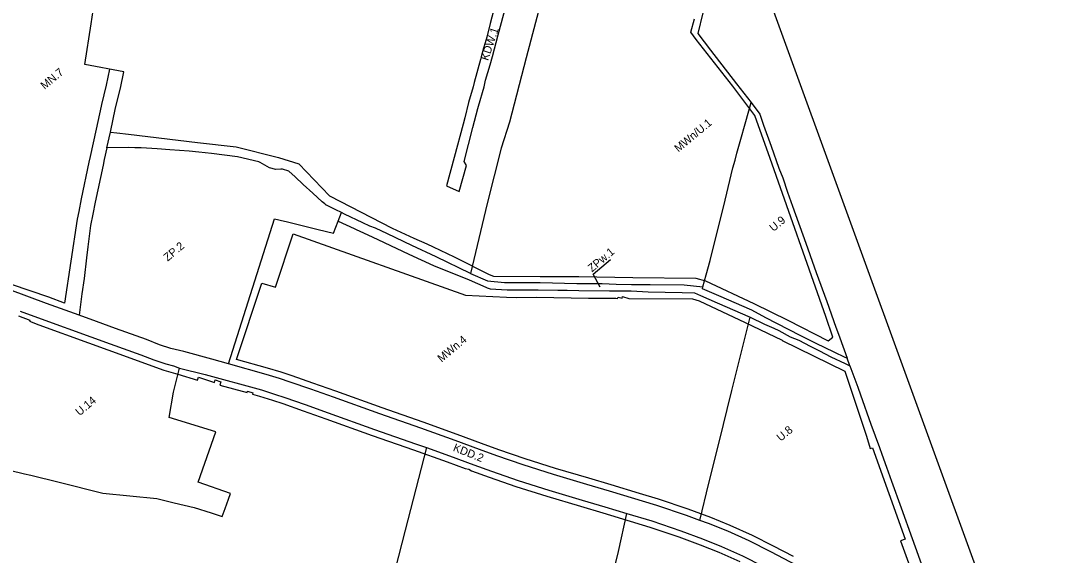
# Model space of a CAD drawing. Extents: x 7418616 to 7420822, y 5550745 to 5553106.
# Drawn here: x 7420140 to 7420789, y 5551619 to 5551953 of the extents above; entities that cross this region are included whole.
import ezdxf

# ---------------------------------------------------------------- set-up
doc = ezdxf.new("R2010")
doc.units = 0
for name, color, linetype in [('granica obszaru objętego planem', 7, 'Continuous'), ('linie rozgraniczające', 7, 'Continuous'), ('nieprzekraczalne linie zabudowy', 7, 'Continuous'), ('przeznaczenia terenów', 7, 'Continuous')]:
    doc.layers.add(name, color=color, linetype=linetype)

msp = doc.modelspace()

# ---------------------------------------------------------------- linework, layer by layer
at = {"layer": 'granica obszaru objętego planem'}
msp.add_lwpolyline([(7420419.04, 5552462.29), (7420427.01, 5552448.46), (7420437.26, 5552429.47), (7420442.19, 5552419.71), (7420448.72, 5552405.7), (7420457.17, 5552386.45), (7420461.96, 5552374), (7420467.81, 5552358.36), (7420579.74, 5552042.73), (7420611.64, 5551954.27), (7420788.95, 5551466.82)], dxfattribs=at)
at = {"layer": 'linie rozgraniczające'}
for p, q in [((7420338.05, 5551827.75), (7420340.15, 5551833.05)), ((7420654.02, 5551747.44), (7420655.91, 5551742.21)), ((7420657.64, 5551737.41), (7420655.91, 5551742.21))]:
    msp.add_line(p, q, dxfattribs=at)
for points in [[(7420419.04, 5552462.29), (7420427.01, 5552448.46), (7420437.26, 5552429.47), (7420442.19, 5552419.71), (7420448.72, 5552405.7), (7420457.17, 5552386.45), (7420461.96, 5552374), (7420467.81, 5552358.36), (7420579.74, 5552042.73), (7420611.64, 5551954.27), (7420788.95, 5551466.82)], [(7420193.57, 5551873.49), (7420195.82, 5551883.31), (7420198.98, 5551898.48), (7420202.06, 5551910.66), (7420204.15, 5551920.87), (7420179.92, 5551925.55), (7420183.78, 5551950.94), (7420185.03, 5551959.25), (7420186.02, 5551965.86), (7420186.46, 5551968.78), (7420187.03, 5551972.47), (7420187.29, 5551974.18), (7420188.03, 5551979.07), (7420190.09, 5551992.79), (7420192.66, 5551992.53), (7420230.5, 5551986.79), (7420231.69, 5551995.09), (7420233, 5552002.11), (7420234.81, 5552008.88), (7420235.65, 5552015.65), (7420235.1, 5552018.04), (7420234.95, 5552018.56), (7420235.55, 5552023.03), (7420237.91, 5552040.62)], [(7420475.4, 5552004.42), (7420468.68, 5551980.21), (7420466.09, 5551970.04), (7420455.5, 5551929.73), (7420444.96, 5551889.52), (7420439.84, 5551873.32), (7420431, 5551838.75), (7420420.77, 5551795.07)], [(7420435.02, 5551959.02), (7420432.98, 5551951.04), (7420430.82, 5551942.66), (7420429.78, 5551938.99), (7420428.82, 5551935.63), (7420427.37, 5551930.37), (7420426.91, 5551928.66), (7420423.07, 5551914.35), (7420422.35, 5551911.64), (7420419.51, 5551901.86), (7420417.16, 5551892.29), (7420416.04, 5551888.17), (7420410.47, 5551867.41), (7420405.72, 5551849.75), (7420413.67, 5551846.22), (7420418.25, 5551862.39), (7420416.7, 5551864.88), (7420422.21, 5551886.13), (7420425.3, 5551898.02), (7420425.69, 5551899.5), (7420429.15, 5551911.64), (7420430.15, 5551915.7), (7420433.02, 5551925.35), (7420434.41, 5551930.56), (7420437.88, 5551943.99), (7420444.41, 5551968.18)], [(7420565.81, 5551957.74), (7420562.67, 5551944.97), (7420570.65, 5551934.55), (7420586.79, 5551913.47), (7420595.95, 5551901.87)], [(7420565.79, 5551786.62), (7420567.78, 5551794.28), (7420570.32, 5551803.16), (7420579.82, 5551840.9), (7420584.55, 5551861.06), (7420585.91, 5551865.75), (7420587.09, 5551870.08), (7420589.19, 5551877.53), (7420592.6, 5551889.95), (7420595.95, 5551901.87)], [(7420595.95, 5551901.87), (7420601.27, 5551894.57), (7420603.59, 5551887.71), (7420608.4, 5551874.62), (7420613.28, 5551860.87), (7420615.75, 5551854.67), (7420618.72, 5551845.89), (7420621.82, 5551837.01), (7420630.07, 5551813.93), (7420635.31, 5551799.28), (7420636.59, 5551795.72), (7420643.11, 5551777.66), (7420648.9, 5551761.61), (7420650.52, 5551757.14), (7420654.02, 5551747.44)], [(7420193.57, 5551873.49), (7420191.9, 5551866.18), (7420191.22, 5551862.75), (7420186.41, 5551839.62), (7420184.95, 5551832.03), (7420183.4, 5551824.97), (7420181.82, 5551811.76), (7420180.97, 5551804.76), (7420179.39, 5551791.89), (7420178, 5551782.42), (7420176.22, 5551769.04)], [(7420340.15, 5551833.05), (7420336.66, 5551834.73), (7420330.73, 5551837.64), (7420330.65, 5551837.7), (7420329.65, 5551838.52), (7420328.15, 5551839.84), (7420322.24, 5551845.23), (7420316.3, 5551850.6), (7420311.16, 5551855.35), (7420307.24, 5551859), (7420303.27, 5551860.19), (7420302.28, 5551860.14), (7420299.19, 5551859.93), (7420295.13, 5551861.02), (7420289.33, 5551864.37), (7420288.45, 5551864.84), (7420275.11, 5551867.93), (7420258.93, 5551869.93), (7420250.97, 5551870.77), (7420245, 5551871.32), (7420239.02, 5551871.84), (7420233.04, 5551872.31), (7420225.06, 5551872.87), (7420215.08, 5551873.53), (7420211.08, 5551873.6), (7420207.08, 5551873.64), (7420193.57, 5551873.49)], [(7420269.61, 5551738.62), (7420298.26, 5551829.25), (7420304.48, 5551827.71), (7420305.49, 5551827.46), (7420314.72, 5551825.19), (7420325.66, 5551822.53)], [(7420420.77, 5551795.07), (7420399.26, 5551805.5), (7420383.96, 5551812.62), (7420368.78, 5551819.84), (7420361.34, 5551823.34), (7420357.85, 5551824.54), (7420353.55, 5551826.64), (7420342.04, 5551832.14), (7420340.15, 5551833.05)], [(7420325.66, 5551822.53), (7420335.05, 5551820.23), (7420338.05, 5551827.75)], [(7420338.05, 5551827.75), (7420347.96, 5551823.13), (7420349.29, 5551822.51), (7420351.53, 5551821.47), (7420359.35, 5551817.88), (7420366.84, 5551814.34), (7420382.19, 5551807.19), (7420397.62, 5551800), (7420419.84, 5551791.08), (7420430.22, 5551786.42), (7420431.1, 5551786.05), (7420432.88, 5551785.53), (7420443.61, 5551784.93), (7420450.46, 5551784.85), (7420462.92, 5551784.91), (7420475.14, 5551784.66), (7420480.97, 5551784.55), (7420488.28, 5551784.42), (7420507.44, 5551784.26), (7420520.99, 5551784.28), (7420531.65, 5551783.6), (7420552.91, 5551783.17), (7420560.66, 5551783.08), (7420564.41, 5551781.27), (7420574.64, 5551776.81), (7420595.34, 5551767.85)], [(7420176.22, 5551769.04), (7420156.02, 5551776.41), (7420132.92, 5551784.81), (7420112.92, 5551791.86), (7420106.31, 5551793.86), (7420104.19, 5551797.21)], [(7420420.77, 5551795.07), (7420431.22, 5551790.39), (7420441.9, 5551789.38), (7420464.16, 5551789.36), (7420487.11, 5551788.86), (7420494.52, 5551788.84), (7420502.91, 5551788.71), (7420511.72, 5551788.46), (7420521.22, 5551788.12), (7420526.02, 5551788.16), (7420532.88, 5551788.27), (7420554.22, 5551787.95), (7420565.79, 5551786.62)], [(7420655.91, 5551742.21), (7420654.66, 5551742.7), (7420647.76, 5551745.87), (7420636.51, 5551751.36), (7420626.5, 5551756.28), (7420605.19, 5551767.47), (7420596.39, 5551772.13), (7420575.73, 5551781.01), (7420565.49, 5551785.45), (7420565.79, 5551786.62)], [(7420139.57, 5551771.54), (7420152.53, 5551766.83), (7420183.58, 5551755.49), (7420195.6, 5551751.2), (7420214.77, 5551744.27), (7420223, 5551741.05), (7420230.5, 5551738.58), (7420235.25, 5551737.38), (7420238.91, 5551736.05)], [(7420269.61, 5551738.62), (7420259.16, 5551741.52), (7420241.71, 5551746.28), (7420233.51, 5551748.33), (7420226.58, 5551750.61), (7420218.3, 5551753.84), (7420199.05, 5551760.79), (7420187.06, 5551765.08), (7420176.22, 5551769.04)], [(7420563.98, 5551640.89), (7420569.57, 5551664.22), (7420577.46, 5551695.58), (7420578.76, 5551700.83), (7420581.07, 5551710.14), (7420583.97, 5551722.05), (7420595.34, 5551767.85)], [(7420595.34, 5551767.85), (7420604.2, 5551763.43), (7420610.07, 5551760.86), (7420613.28, 5551759.43), (7420620.32, 5551755.53), (7420625.76, 5551753.4), (7420632.88, 5551749.62), (7420638.56, 5551746.67), (7420645.76, 5551743.03), (7420654.57, 5551738.81), (7420657.64, 5551737.41)], [(7420563.98, 5551640.89), (7420555.52, 5551644.01), (7420536.95, 5551650.29), (7420507.42, 5551659.25), (7420493.38, 5551663.35), (7420472.58, 5551669.53), (7420453.64, 5551675.59), (7420437.14, 5551681.27), (7420426.25, 5551685.16), (7420411.05, 5551690.86), (7420389.71, 5551698.42), (7420364.1, 5551707.37), (7420335.16, 5551717.75), (7420320.95, 5551722.8), (7420308.12, 5551727.3), (7420301.33, 5551729.53), (7420293.04, 5551732.1), (7420269.61, 5551738.62)], [(7420657.64, 5551737.41), (7420657.66, 5551737.35), (7420662.48, 5551723.99), (7420664.17, 5551719.3), (7420670.77, 5551701.04), (7420676.02, 5551686.48), (7420677.51, 5551682.36), (7420680.54, 5551674.12), (7420683.66, 5551665.32), (7420689.62, 5551648.81), (7420696.56, 5551629.55), (7420703.22, 5551611.13), (7420709.97, 5551592.42), (7420716.81, 5551573.46), (7420715.46, 5551565.97)], [(7420118.45, 5551675.77), (7420123.97, 5551674.44), (7420142.25, 5551670.08), (7420146.23, 5551669.09), (7420163.91, 5551664.7), (7420191.08, 5551657.95), (7420224.74, 5551654.62), (7420235.68, 5551651.83), (7420248.2, 5551648.89), (7420258.83, 5551645.64), (7420259.47, 5551645.41), (7420265.63, 5551643.27), (7420267.41, 5551648.29), (7420269.47, 5551654.1), (7420270.73, 5551657.71), (7420250.63, 5551664.82), (7420261.72, 5551696.13), (7420232.55, 5551705.25), (7420235.19, 5551721.06), (7420238.91, 5551736.05)], [(7420238.91, 5551736.05), (7420255.01, 5551732.08), (7420290.09, 5551722.34), (7420298.27, 5551719.8), (7420304.85, 5551717.64), (7420317.55, 5551713.18), (7420331.73, 5551708.14), (7420360.68, 5551697.76), (7420386.33, 5551688.8), (7420393.2, 5551686.36)], [(7420393.2, 5551686.36), (7420379.89, 5551634.75), (7420369.22, 5551593.33), (7420349.6, 5551520.43), (7420344.48, 5551500.75)], [(7420393.2, 5551686.36), (7420407.51, 5551681.29), (7420422.79, 5551675.56), (7420433.79, 5551671.64), (7420450.47, 5551665.89), (7420469.52, 5551659.79), (7420490.5, 5551653.57), (7420504.48, 5551649.48), (7420518.37, 5551645.27)], [(7420470.48, 5551450.29), (7420474.34, 5551465.31), (7420489.31, 5551524.58), (7420494.68, 5551545.81), (7420494.71, 5551545.91), (7420503.09, 5551580.48), (7420513.15, 5551621.48), (7420518.37, 5551645.27)], [(7420518.37, 5551645.27), (7420533.91, 5551640.55), (7420552.06, 5551634.41), (7420565.64, 5551629.41), (7420577.38, 5551624.71), (7420590.52, 5551618.8), (7420603.34, 5551612.34)], [(7420715.46, 5551565.97), (7420680.95, 5551583.37), (7420641.65, 5551603.74), (7420620.61, 5551614.78), (7420608.14, 5551621.35), (7420594.81, 5551628.06), (7420581.33, 5551634.12), (7420569.37, 5551638.91), (7420563.98, 5551640.89)]]:
    msp.add_lwpolyline(points, dxfattribs=at)
at = {"layer": 'nieprzekraczalne linie zabudowy'}
for points in [[(7420195.82, 5551883.31), (7420199.93, 5551882.85), (7420207.2, 5551881.99), (7420250.28, 5551876.86), (7420274.29, 5551874.07), (7420300.78, 5551867.36), (7420313.59, 5551863.44), (7420332.58, 5551843.56), (7420371.68, 5551823.4), (7420385.24, 5551817.19), (7420393.44, 5551813.58), (7420397.34, 5551811.78), (7420410.41, 5551805.36), (7420432.38, 5551794.5), (7420435.06, 5551793.46), (7420464.26, 5551793.27), (7420488.34, 5551793.19), (7420522.04, 5551792.5), (7420561.31, 5551792.08), (7420567.48, 5551790.37), (7420597.6, 5551776.38), (7420618.88, 5551765.84), (7420644.08, 5551752.93), (7420647.04, 5551755.24), (7420642.66, 5551768.19), (7420607.86, 5551866.8), (7420598.3, 5551893.78), (7420584.42, 5551911.93), (7420561.51, 5551941.19), (7420558.22, 5551945.61), (7420560.49, 5551954.08)], [(7420195.31, 5551922.58), (7420193.28, 5551912.67), (7420190.24, 5551900.61), (7420190, 5551899.61), (7420187.03, 5551885.23), (7420183.1, 5551868.06), (7420182.4, 5551864.54), (7420177.63, 5551841.56), (7420176.14, 5551833.85), (7420175.05, 5551828.89), (7420167.2, 5551776.59), (7420157.4, 5551780.17), (7420122.15, 5551792.15)], [(7420274.65, 5551741.37), (7420290.29, 5551789.03), (7420299.02, 5551786.45), (7420309.88, 5551819.73), (7420417.58, 5551781.56), (7420443.13, 5551780.25), (7420449.42, 5551780.09), (7420461.99, 5551780.36), (7420494.37, 5551779.7), (7420511.54, 5551779.56), (7420512.52, 5551779.47), (7420512.82, 5551780.21), (7420515.37, 5551779.57), (7420515.61, 5551780.6), (7420519.53, 5551779.5), (7420559.32, 5551779.18), (7420563.48, 5551777.9), (7420592.16, 5551764.54), (7420615.24, 5551753.33), (7420615.34, 5551753.32), (7420654.4, 5551734.12), (7420667.9, 5551693.43), (7420670.34, 5551685.89), (7420671.63, 5551686.3), (7420692.2, 5551629.25), (7420689.3, 5551628.15), (7420695.9, 5551609.77)], [(7420138.46, 5551768.6), (7420145.51, 5551766), (7420145.23, 5551765.22), (7420151.16, 5551763.07), (7420182.24, 5551751.72), (7420194.25, 5551747.43), (7420229.25, 5551734.78), (7420237.95, 5551732.17), (7420250.22, 5551728.44), (7420250.9, 5551730.38), (7420260.89, 5551727.05), (7420261.33, 5551728.72), (7420264.82, 5551727.44), (7420264.13, 5551725.4), (7420281.14, 5551720.67), (7420281.4, 5551721.56), (7420284.84, 5551720.62), (7420284.61, 5551719.71), (7420288.96, 5551718.5), (7420297.05, 5551715.99), (7420303.56, 5551713.85), (7420316.23, 5551709.41), (7420330.38, 5551704.37), (7420359.36, 5551693.98), (7420385, 5551685.02), (7420406.14, 5551677.53), (7420417.29, 5551673.35), (7420419.59, 5551672.88), (7420421.34, 5551671.83), (7420432.42, 5551667.88), (7420449.06, 5551662.14), (7420468.3, 5551655.98), (7420489.36, 5551649.73), (7420503.35, 5551645.64), (7420532.68, 5551636.75), (7420550.73, 5551630.64), (7420564.21, 5551625.68), (7420575.82, 5551621.03), (7420588.8, 5551615.19)], [(7420622.47, 5551618.32), (7420609.97, 5551624.91), (7420596.74, 5551631.57), (7420582.86, 5551637.82), (7420570.8, 5551642.64), (7420556.68, 5551647.84), (7420538.11, 5551654.12), (7420526.21, 5551657.74), (7420508.58, 5551663.07), (7420494.51, 5551667.19), (7420473.76, 5551673.35), (7420454.9, 5551679.38), (7420438.46, 5551685.05), (7420427.63, 5551688.91), (7420412.42, 5551694.62), (7420391.06, 5551702.19), (7420365.44, 5551711.14), (7420336.51, 5551721.51), (7420322.3, 5551726.57), (7420309.41, 5551731.09), (7420302.52, 5551733.35), (7420293.97, 5551736), (7420274.65, 5551741.37)]]:
    msp.add_lwpolyline(points, dxfattribs=at)
at = {"layer": 'przeznaczenia terenów'}
msp.add_lwpolyline([(7420501.66, 5551786.42), (7420497.36, 5551794.7), (7420508.12, 5551803.77)], dxfattribs=at)

# ---------------------------------------------------------------- texts
for s, rotation, p in [('KDW.1', 71.48365, (7420431.66, 5551927.57)), ('MN.7', 39.84394, (7420154.78, 5551909.64)), ('MWn/U.1', 39.84394, (7420550.54, 5551870.49)), ('U.9', 39.84394, (7420609.88, 5551820.89)), ('ZP.2', 39.84394, (7420231.6, 5551802.39)), ('ZPw.1', 40.1, (7420496.55, 5551795.66)), ('MWn.4', 39.84394, (7420402.61, 5551739.39)), ('U.14', 39.84394, (7420176.56, 5551705.92)), ('U.8', 39.84394, (7420614.41, 5551689.97)), ('KDD.2', 338.42992, (7420409.4, 5551684.45))]:
    msp.add_text(s, height=5, rotation=rotation, dxfattribs=at).set_placement(p)

doc.saveas('drawing.dxf')
